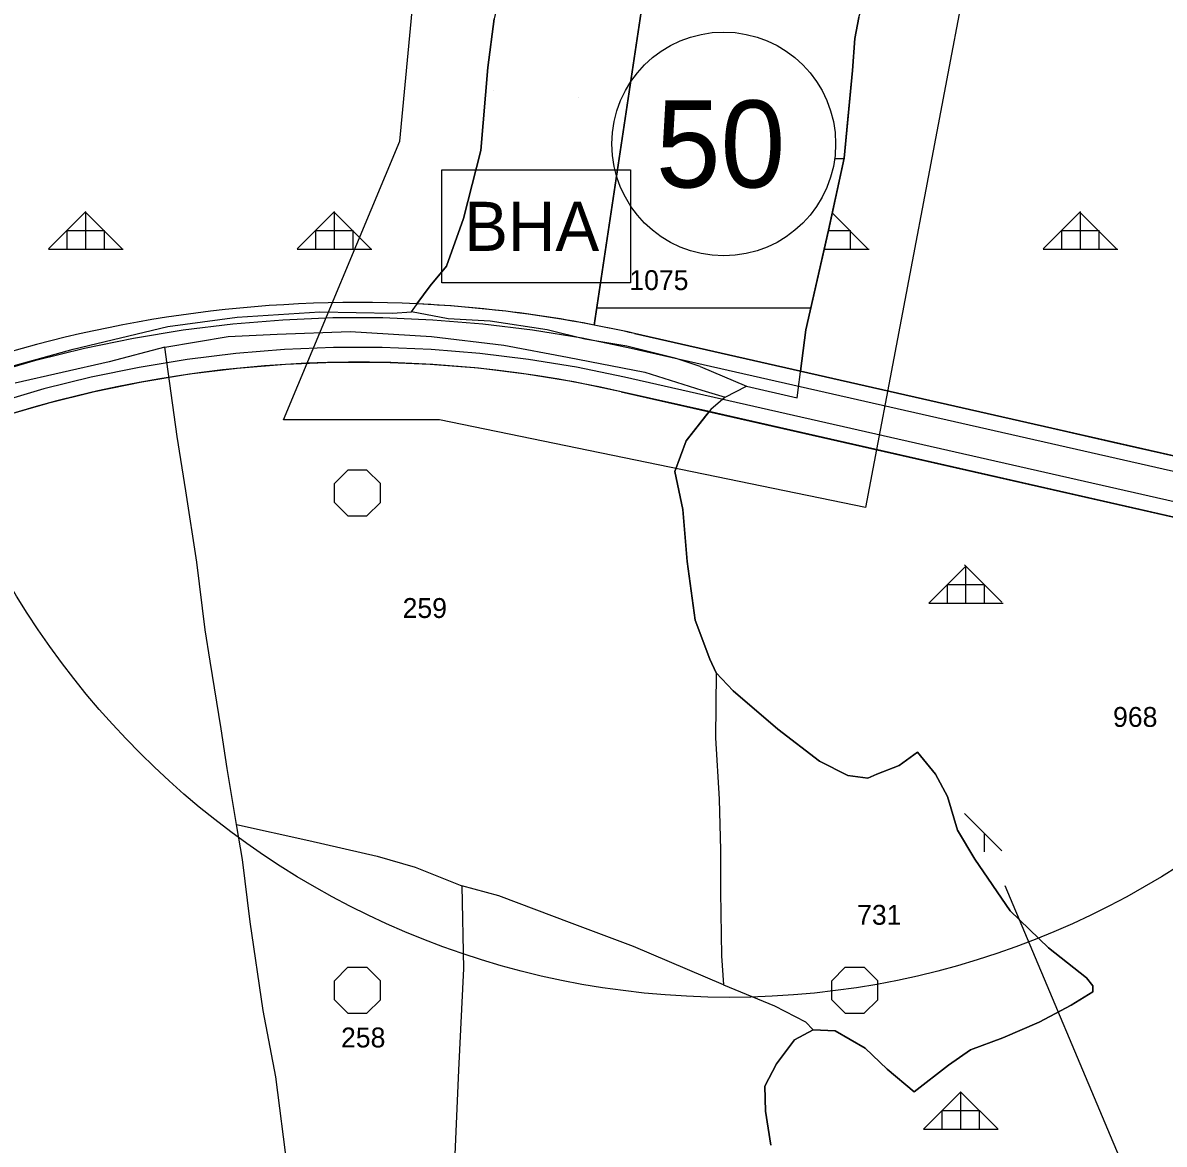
# Model space of a CAD drawing. Extents: x 410727 to 412947, y 4463506 to 4466382.
# Drawn here: x 411331.1 to 411560.6, y 4465556.3 to 4465781.8 of the extents above; entities that cross this region are included whole.
import ezdxf

# ---------------------------------------------------------------- set-up
doc = ezdxf.new("R2010")
doc.units = 0
for name, color, linetype in [('ADAKENARI', 7, 'Continuous'), ('KALDIRIM', 7, 'Continuous'), ('KDS_PARSEL_NO', 7, 'Continuous'), ('KDS_PL', 7, 'Continuous'), ('LJ_ÇERÇEVE', 7, 'Continuous'), ('PL_AYA_ORMAN', 7, 'Continuous'), ('PL_GELİŞME_KONUT', 7, 'Continuous'), ('PL_K_BHA', 7, 'Continuous'), ('PL_KA_TARIM_DIGER', 7, 'Continuous'), ('sembol', 7, 'Continuous'), ('SN_ONAMA', 7, 'Continuous'), ('TR_GELİŞME_KONUT_ÇOKAZ', 7, 'Continuous'), ('TR_ORMAN', 7, 'Continuous'), ('TR_SU_DEPOSU', 7, 'Continuous'), ('TR_TARIMALANI', 7, 'Continuous')]:
    doc.layers.add(name, color=color, linetype=linetype)

msp = doc.modelspace()

# ---------------------------------------------------------------- linework, layer by layer
at = {"layer": 'ADAKENARI'}
for p, q in [((411456.62, 4465792.14), (411445.98, 4465721.04)), ((411487.47, 4465711.77), (411454.07, 4465719.35)), ((411487.47, 4465711.77), (411454.07, 4465719.35)), ((411537.97, 4465700.31), (411487.47, 4465711.77)), ((411584.92, 4465689.65), (411487.47, 4465711.77)), ((411451.42, 4465707.64), (411569.91, 4465680.75)), ((411464.49, 4465697.73), (411469.07, 4465703.64)), ((411581.57, 4465678.11), (411469.07, 4465703.64)), ((411581.57, 4465678.11), (411469.07, 4465703.64)), ((411572.56, 4465692.45), (411537.97, 4465700.31)), ((411462.18, 4465691.6), (411464.49, 4465697.73)), ((411463.78, 4465683.97), (411462.18, 4465691.6)), ((411464.69, 4465673.53), (411463.78, 4465683.97)), ((411466.29, 4465661.68), (411464.69, 4465673.53)), ((411469.2, 4465653.84), (411466.29, 4465661.68)), ((411470.5, 4465651.13), (411469.2, 4465653.84)), ((411473.91, 4465647.51), (411470.5, 4465651.13)), ((411482.93, 4465639.78), (411473.91, 4465647.51)), ((411491.25, 4465633.35), (411482.93, 4465639.78)), ((411510.99, 4465635.16), (411507.29, 4465632.45)), ((411514.6, 4465630.74), (411510.99, 4465635.16)), ((411496.96, 4465630.44), (411491.25, 4465633.35)), ((411507.29, 4465632.45), (411502.78, 4465630.74)), ((411500.97, 4465629.94), (411496.96, 4465630.44)), ((411502.78, 4465630.74), (411500.97, 4465629.94)), ((411517.01, 4465626.22), (411514.6, 4465630.74)), ((411519.01, 4465619.5), (411517.01, 4465626.22)), ((411522.52, 4465613.67), (411519.01, 4465619.5)), ((411529.64, 4465603.23), (411522.52, 4465613.67)), ((411537.35, 4465595.79), (411529.64, 4465603.23)), ((411544.97, 4465589.77), (411537.35, 4465595.79)), ((411546.28, 4465588.16), (411544.97, 4465589.77)), ((411546.28, 4465586.96), (411546.28, 4465588.16)), ((411541.86, 4465584.25), (411546.28, 4465586.96)), ((411535.45, 4465580.83), (411541.86, 4465584.25)), ((411486.24, 4465577.32), (411490.04, 4465579.33)), ((411486.24, 4465577.32), (411490.04, 4465579.33)), ((411490.04, 4465579.33), (411494.46, 4465579.12)), ((411490.04, 4465579.33), (411494.46, 4465579.12)), ((411494.46, 4465579.12), (411500.47, 4465575.61)), ((411528.13, 4465577.72), (411535.45, 4465580.83)), ((411482.63, 4465572.5), (411486.24, 4465577.32)), ((411521.62, 4465575.31), (411528.13, 4465577.72)), ((411500.47, 4465575.61), (411504.88, 4465571.39)), ((411517.21, 4465572.19), (411521.62, 4465575.31)), ((411480.32, 4465567.98), (411482.63, 4465572.5)), ((411510.29, 4465566.87), (411517.21, 4465572.19)), ((411504.88, 4465571.39), (411510.29, 4465566.87)), ((411480.42, 4465562.96), (411480.32, 4465567.98)), ((411481.53, 4465556.12), (411480.42, 4465562.96))]:
    msp.add_line(p, q, dxfattribs=at)
for points in [[(411410.34, 4465725.3), (411412.98, 4465728.93), (411416.28, 4465732.86), (411419.73, 4465742.46), (411423.19, 4465756.15), (411424.6, 4465772.83), (411425.86, 4465782.59)], [(411499.2, 4465782.9), (411498.42, 4465778.65), (411497.95, 4465772.2), (411496.85, 4465761.03), (411496.22, 4465754.58), (411493.07, 4465740.04), (411488.52, 4465720.11), (411487.47, 4465711.77)]]:
    msp.add_lwpolyline(points, dxfattribs=at)
for radius, start, end in [(251.25, 87.2905, 108.9831), (251.25, 77.2133, 87.2905), (251.25, 77.2133, 87.2905), (239.25, 77.2133, 109.7719)]:
    msp.add_arc((411398.47, 4465474.33), radius, start, end, dxfattribs=at)
at = {"layer": 'KALDIRIM'}
for points in [[(411324.04, 4465711.16), (411333.71, 4465713.98), (411343.49, 4465716.41), (411353.36, 4465718.44), (411363.3, 4465720.07), (411373.3, 4465721.3), (411383.34, 4465722.12), (411393.41, 4465722.53), (411403.49, 4465722.53), (411413.55, 4465722.12), (411423.6, 4465721.3), (411433.6, 4465720.08), (411443.54, 4465718.45), (411453.41, 4465716.42), (411571.9, 4465689.53)], [(411570.57, 4465683.68), (411452.08, 4465710.57), (411442.45, 4465712.55), (411432.75, 4465714.14), (411422.99, 4465715.33), (411413.19, 4465716.13), (411403.37, 4465716.53), (411393.53, 4465716.53), (411383.71, 4465716.13), (411373.91, 4465715.33), (411364.15, 4465714.13), (411354.45, 4465712.54), (411344.82, 4465710.56), (411335.28, 4465708.19), (411325.84, 4465705.43)]]:
    msp.add_lwpolyline(points, dxfattribs=at)
at = {"layer": 'KDS_PL'}
for p, q in [((411424.6, 4465772.83), (411425.86, 4465782.59)), ((411498.42, 4465778.65), (411499.2, 4465782.9)), ((411497.95, 4465772.2), (411498.42, 4465778.65)), ((411423.19, 4465756.15), (411424.6, 4465772.83)), ((411496.85, 4465761.03), (411497.95, 4465772.2)), ((411496.22, 4465754.58), (411496.85, 4465761.03)), ((411419.73, 4465742.46), (411423.19, 4465756.15)), ((411493.08, 4465740.1), (411496.22, 4465754.58)), ((411416.28, 4465732.86), (411419.73, 4465742.46)), ((411488.52, 4465720.11), (411493.08, 4465740.1)), ((411412.98, 4465728.93), (411416.28, 4465732.86)), ((411409.21, 4465723.73), (411412.98, 4465728.93)), ((411374.19, 4465722.63), (411390.84, 4465723.73)), ((411390.84, 4465723.73), (411405.44, 4465723.42)), ((411405.44, 4465723.42), (411409.21, 4465723.73)), ((411416.59, 4465722.32), (411409.21, 4465723.73)), ((411360.21, 4465720.75), (411374.19, 4465722.63)), ((411425.07, 4465721.84), (411416.59, 4465722.32)), ((411436.54, 4465720.11), (411425.07, 4465721.84)), ((411341.21, 4465716.18), (411360.21, 4465720.75)), ((411372.37, 4465718.72), (411382.2, 4465719.22)), ((411382.2, 4465719.22), (411396.93, 4465719.72)), ((411396.93, 4465719.72), (411413.27, 4465718.72)), ((411444.08, 4465718.22), (411436.54, 4465720.11)), ((411486.8, 4465706.42), (411488.52, 4465720.11)), ((411359.64, 4465716.61), (411348.46, 4465713.65)), ((411359.64, 4465716.61), (411372.37, 4465718.72)), ((411360.34, 4465711.69), (411359.64, 4465716.61)), ((411413.27, 4465718.72), (411427.8, 4465717.01)), ((411427.8, 4465717.01), (411440.63, 4465714.6)), ((411452.56, 4465716.81), (411444.08, 4465718.22)), ((411462.45, 4465714.29), (411452.56, 4465716.81)), ((411317.33, 4465709.57), (411341.21, 4465716.18)), ((411440.63, 4465714.6), (411456.17, 4465711.59)), ((411467.32, 4465712.72), (411462.45, 4465714.29)), ((411348.46, 4465713.65), (411329.56, 4465709.38)), ((411467.32, 4465712.72), (411476.59, 4465708.78)), ((411362.15, 4465698.63), (411360.34, 4465711.69)), ((411456.17, 4465711.59), (411467.59, 4465707.97)), ((411467.59, 4465707.97), (411472.3, 4465706.57)), ((411472.3, 4465706.57), (411476.59, 4465708.78)), ((411476.59, 4465708.78), (411486.8, 4465706.42)), ((411472.3, 4465706.57), (411469.4, 4465704.06)), ((411469.4, 4465704.06), (411464.49, 4465697.73)), ((411363.85, 4465687.69), (411362.15, 4465698.63)), ((411464.49, 4465697.73), (411462.18, 4465691.6)), ((411462.18, 4465691.6), (411463.78, 4465683.97)), ((411366.06, 4465673.33), (411363.85, 4465687.69)), ((411463.78, 4465683.97), (411464.69, 4465673.53)), ((411367.76, 4465659.77), (411366.06, 4465673.33)), ((411464.69, 4465673.53), (411466.29, 4465661.68)), ((411466.29, 4465661.68), (411469.2, 4465653.84)), ((411368.76, 4465653.44), (411367.76, 4465659.77)), ((411370.97, 4465639.88), (411368.76, 4465653.44)), ((411469.2, 4465653.84), (411470.5, 4465651.13)), ((411470.5, 4465651.13), (411470.4, 4465638.07)), ((411473.91, 4465647.51), (411470.5, 4465651.13)), ((411482.93, 4465639.78), (411473.91, 4465647.51)), ((411372.17, 4465631.85), (411370.97, 4465639.88)), ((411491.25, 4465633.35), (411482.93, 4465639.78)), ((411470.4, 4465638.07), (411471.1, 4465625.72)), ((411510.99, 4465635.16), (411507.29, 4465632.45)), ((411514.6, 4465630.74), (411510.99, 4465635.16)), ((411374.08, 4465620.6), (411372.17, 4465631.85)), ((411496.96, 4465630.44), (411491.25, 4465633.35)), ((411507.29, 4465632.45), (411502.78, 4465630.74)), ((411500.97, 4465629.94), (411496.96, 4465630.44)), ((411502.78, 4465630.74), (411500.97, 4465629.94)), ((411517.01, 4465626.22), (411514.6, 4465630.74)), ((411471.1, 4465625.72), (411471.4, 4465615.48)), ((411519.01, 4465619.5), (411517.01, 4465626.22)), ((411375.28, 4465613.57), (411374.08, 4465620.6)), ((411374.08, 4465620.6), (411388.61, 4465617.39)), ((411522.52, 4465613.67), (411519.01, 4465619.5)), ((411388.61, 4465617.39), (411402.34, 4465614.27)), ((411376.78, 4465601.02), (411375.28, 4465613.57)), ((411402.34, 4465614.27), (411409.96, 4465612.06)), ((411471.4, 4465615.48), (411471.4, 4465607.04)), ((411529.64, 4465603.23), (411522.52, 4465613.67)), ((411409.96, 4465612.06), (411419.38, 4465608.25)), ((411426.8, 4465606.24), (411419.38, 4465608.25)), ((411419.38, 4465608.25), (411419.68, 4465591.68)), ((411471.4, 4465607.04), (411471.6, 4465594.19)), ((411441.53, 4465600.72), (411426.8, 4465606.24)), ((411537.35, 4465595.79), (411529.64, 4465603.23)), ((411379.39, 4465583.24), (411376.78, 4465601.02)), ((411453.86, 4465596.1), (411441.53, 4465600.72)), ((411472, 4465588.36), (411453.86, 4465596.1)), ((411544.97, 4465589.77), (411537.35, 4465595.79)), ((411471.6, 4465594.19), (411472, 4465588.36)), ((411419.68, 4465591.68), (411418.68, 4465571.19)), ((411472, 4465588.36), (411482.23, 4465584.14)), ((411546.28, 4465588.16), (411544.97, 4465589.77)), ((411546.28, 4465586.96), (411546.28, 4465588.16)), ((411541.86, 4465584.25), (411546.28, 4465586.96)), ((411482.23, 4465584.14), (411488.44, 4465580.93)), ((411535.45, 4465580.83), (411541.86, 4465584.25)), ((411381.99, 4465569.88), (411379.39, 4465583.24)), ((411486.24, 4465577.32), (411490.04, 4465579.33)), ((411488.44, 4465580.93), (411490.04, 4465579.33)), ((411490.04, 4465579.33), (411494.46, 4465579.12)), ((411494.46, 4465579.12), (411500.47, 4465575.61)), ((411528.13, 4465577.72), (411535.45, 4465580.83)), ((411482.63, 4465572.5), (411486.24, 4465577.32)), ((411521.62, 4465575.31), (411528.13, 4465577.72)), ((411500.47, 4465575.61), (411504.88, 4465571.39)), ((411517.21, 4465572.19), (411521.62, 4465575.31)), ((411480.32, 4465567.98), (411482.63, 4465572.5)), ((411510.29, 4465566.87), (411517.21, 4465572.19)), ((411384.3, 4465551.5), (411381.99, 4465569.88)), ((411418.68, 4465571.19), (411417.78, 4465550.1)), ((411504.88, 4465571.39), (411510.29, 4465566.87)), ((411480.42, 4465562.96), (411480.32, 4465567.98)), ((411481.53, 4465556.12), (411480.42, 4465562.96))]:
    msp.add_line(p, q, dxfattribs=at)
at = {"layer": 'LJ_ÇERÇEVE'}
msp.add_line((412177.76, 4464068.35), (411528.62, 4465608.26), dxfattribs=at)
msp.add_circle((411473.17, 4465753.45), 167.6, dxfattribs=at)
at = {"layer": 'PL_AYA_ORMAN'}
for points in [[(411410.34, 4465725.3), (411410.34, 4465725.3), (411410.34, 4465725.3), (411412.98, 4465728.93), (411416.28, 4465732.86), (411419.73, 4465742.46), (411423.19, 4465756.15), (411424.6, 4465772.83), (411425.86, 4465782.59)], [(411499.2, 4465782.9), (411498.42, 4465778.65), (411497.95, 4465772.2), (411496.22, 4465754.58), (411493.08, 4465740.1), (411488.52, 4465720.11), (411487.47, 4465711.77), (411537.97, 4465700.31), (411550.26, 4465697.52), (411572.56, 4465692.45), (411584.92, 4465689.65), (411603.17, 4465683.15), (411648.41, 4465667.03), (411663.23, 4465672.82), (411665.57, 4465677.27)], [(411569.91, 4465680.75), (411469.07, 4465703.64), (411464.49, 4465697.73), (411462.18, 4465691.6), (411463.78, 4465683.97), (411464.69, 4465673.53), (411466.29, 4465661.68), (411469.2, 4465653.84), (411470.5, 4465651.13), (411473.91, 4465647.51), (411482.93, 4465639.78), (411491.25, 4465633.35), (411496.96, 4465630.44), (411500.97, 4465629.94), (411502.78, 4465630.74), (411507.29, 4465632.45), (411510.99, 4465635.16), (411514.6, 4465630.74), (411517.01, 4465626.22), (411519.01, 4465619.5), (411522.52, 4465613.67), (411529.64, 4465603.23), (411537.35, 4465595.79), (411544.97, 4465589.77), (411546.28, 4465588.16), (411546.28, 4465586.96), (411541.86, 4465584.25), (411535.45, 4465580.83), (411528.13, 4465577.72), (411521.62, 4465575.31), (411517.21, 4465572.19), (411510.29, 4465566.87), (411504.88, 4465571.39), (411500.47, 4465575.61), (411494.46, 4465579.12), (411490.04, 4465579.33), (411486.24, 4465577.32), (411482.63, 4465572.5), (411480.32, 4465567.98), (411480.42, 4465562.96), (411481.53, 4465556.12)]]:
    msp.add_lwpolyline(points, dxfattribs=at)
msp.add_arc((411398.47, 4465474.33), 251.25, 87.2906, 108.9831, dxfattribs=at)
at = {"layer": 'PL_GELİŞME_KONUT'}
msp.add_lwpolyline([(411454.07, 4465719.35), (411454.07, 4465719.35), (411487.47, 4465711.77), (411488.52, 4465720.11), (411493.07, 4465740.04), (411493.07, 4465740.06), (411493.08, 4465740.1), (411496.22, 4465754.58), (411496.85, 4465761.03), (411497.95, 4465772.2), (411498.42, 4465778.65), (411499.2, 4465782.9), (411500.15, 4465786.21), (411497.5, 4465787.74), (411496.06, 4465788.57), (411494.49, 4465789.35), (411483.97, 4465792.19), (411478.16, 4465792.03), (411465.59, 4465792.34), (411456.62, 4465792.12), (411445.98, 4465721.04), (411445.98, 4465721.04)], dxfattribs=at)
msp.add_arc((411398.47, 4465474.33), 251.25, 77.2133, 79.099, dxfattribs=at)
at = {"layer": 'PL_K_BHA'}
msp.add_lwpolyline([(411445.98, 4465721.04), (411456.62, 4465792.12), (411452.87, 4465792.03), (411440.46, 4465789.51), (411433.96, 4465787.81), (411426.64, 4465785.89), (411425.86, 4465782.59), (411424.6, 4465772.83), (411423.19, 4465756.15), (411419.73, 4465742.46), (411416.28, 4465732.86), (411412.98, 4465728.93), (411410.34, 4465725.3), (411410.34, 4465725.3)], dxfattribs=at)
msp.add_arc((411398.47, 4465474.33), 251.25, 79.099, 87.2905, dxfattribs=at)
at = {"layer": 'PL_KA_TARIM_DIGER'}
for points in [[(411469.07, 4465703.64), (411451.42, 4465707.64), (411441.91, 4465709.6), (411432.32, 4465711.17), (411422.69, 4465712.35), (411413.01, 4465713.13), (411403.31, 4465713.53), (411393.59, 4465713.53), (411383.89, 4465713.13), (411374.21, 4465712.34), (411364.58, 4465711.16), (411354.99, 4465709.59), (411345.48, 4465707.64), (411336.06, 4465705.29), (411326.74, 4465702.57)], [(411481.53, 4465556.12), (411480.42, 4465562.96), (411480.32, 4465567.98), (411482.63, 4465572.5), (411486.24, 4465577.32), (411490.04, 4465579.33), (411494.46, 4465579.12), (411500.47, 4465575.61), (411504.88, 4465571.39), (411510.29, 4465566.87), (411517.21, 4465572.19), (411521.62, 4465575.31), (411528.13, 4465577.72), (411535.45, 4465580.83), (411541.86, 4465584.25), (411546.28, 4465586.96), (411546.28, 4465588.16), (411544.97, 4465589.77), (411537.35, 4465595.79), (411529.64, 4465603.23), (411522.52, 4465613.67), (411519.01, 4465619.5), (411517.01, 4465626.22), (411514.6, 4465630.74), (411510.99, 4465635.16), (411507.29, 4465632.45), (411502.78, 4465630.74), (411500.97, 4465629.94), (411496.96, 4465630.44), (411491.25, 4465633.35), (411482.93, 4465639.78), (411473.91, 4465647.51), (411470.5, 4465651.13), (411469.2, 4465653.84), (411466.29, 4465661.68), (411464.69, 4465673.53), (411463.78, 4465683.97), (411462.18, 4465691.6), (411464.49, 4465697.73), (411469.07, 4465703.64)]]:
    msp.add_lwpolyline(points, dxfattribs=at)
at = {"layer": 'sembol'}
for p, q in [((411415.33, 4465752.29), (411453.29, 4465752.29)), ((411415.33, 4465729.51), (411415.33, 4465752.29)), ((411453.29, 4465752.29), (411453.29, 4465729.51)), ((411453.29, 4465729.51), (411415.33, 4465729.51))]:
    msp.add_line(p, q, dxfattribs=at)
msp.add_circle((411472.03, 4465757.46), 22.5, dxfattribs=at)
at = {"layer": 'SN_ONAMA'}
msp.add_lwpolyline([(411383.47, 4465701.98), (411406.89, 4465758.05), (411410.6, 4465797.01), (411446.38, 4465807.63), (411485.88, 4465807.28), (411522.02, 4465797.82), (411500.54, 4465684.33), (411414.88, 4465701.98)], close=True, dxfattribs=at)
at = {"layer": 'TR_GELİŞME_KONUT_ÇOKAZ'}
for p, q in [((411494.34, 4465754.54), (411496.22, 4465754.54)), ((411446.5, 4465724.54), (411489.53, 4465724.54))]:
    msp.add_line(p, q, dxfattribs=at)
at = {"layer": 'TR_ORMAN'}
for p, q in [((411336.24, 4465736.37), (411343.74, 4465743.87)), ((411351.12, 4465736.31), (411343.62, 4465743.81)), ((411343.75, 4465736.29), (411343.75, 4465743.79)), ((411386.24, 4465736.38), (411393.74, 4465743.88)), ((411401.11, 4465736.31), (411393.61, 4465743.81)), ((411393.75, 4465736.29), (411393.75, 4465743.79)), ((411501.1, 4465736.31), (411493.83, 4465743.58)), ((411536.24, 4465736.4), (411543.74, 4465743.9)), ((411551.09, 4465736.31), (411543.59, 4465743.81)), ((411543.75, 4465736.29), (411543.75, 4465743.79)), ((411340, 4465736.29), (411340, 4465740.04)), ((411340, 4465740.04), (411347.5, 4465740.04)), ((411347.5, 4465736.29), (411347.5, 4465740.04)), ((411390, 4465736.29), (411390, 4465740.04)), ((411390, 4465740.04), (411397.5, 4465740.04)), ((411397.5, 4465736.29), (411397.5, 4465740.04)), ((411493.07, 4465740.04), (411497.5, 4465740.04)), ((411497.5, 4465736.29), (411497.5, 4465740.04)), ((411540, 4465736.29), (411540, 4465740.04)), ((411540, 4465740.04), (411547.5, 4465740.04)), ((411547.5, 4465736.29), (411547.5, 4465740.04)), ((411336.25, 4465736.29), (411351.25, 4465736.29)), ((411386.25, 4465736.29), (411401.25, 4465736.29)), ((411492.21, 4465736.29), (411501.25, 4465736.29)), ((411536.25, 4465736.29), (411551.25, 4465736.29)), ((411513.24, 4465665.09), (411520.74, 4465672.59)), ((411527.93, 4465665.35), (411520.44, 4465672.85)), ((411520.74, 4465665.13), (411520.74, 4465672.63)), ((411516.99, 4465665.13), (411516.99, 4465668.88)), ((411516.99, 4465668.88), (411524.49, 4465668.88)), ((411524.49, 4465665.13), (411524.49, 4465668.88)), ((411513.24, 4465665.13), (411528.24, 4465665.13)), ((411527.97, 4465615.33), (411520.47, 4465622.83)), ((411524.49, 4465615.13), (411524.49, 4465618.88)), ((411512.18, 4465559.36), (411519.68, 4465566.86)), ((411527.14, 4465559.38), (411519.64, 4465566.88)), ((411519.68, 4465559.36), (411519.68, 4465566.86)), ((411515.93, 4465563.11), (411523.43, 4465563.11)), ((411515.93, 4465559.36), (411515.93, 4465563.11)), ((411523.43, 4465559.36), (411523.43, 4465563.11)), ((411512.18, 4465559.36), (411527.18, 4465559.36))]:
    msp.add_line(p, q, dxfattribs=at)
at = {"layer": 'TR_SU_DEPOSU'}
for p, q in [((411425.65, 4465768.19), (411425.65, 4465768.19)), ((411442.85, 4465766.87), (411442.85, 4465766.87)), ((411425.65, 4465743.19), (411425.65, 4465743.19)), ((411442.85, 4465741.87), (411442.85, 4465741.87))]:
    msp.add_line(p, q, dxfattribs=at)
at = {"layer": 'TR_TARIMALANI'}
for p, q in [((411393.75, 4465689.19), (411396.45, 4465691.89)), ((411393.75, 4465689.19), (411396.45, 4465691.89)), ((411396.46, 4465691.9), (411400.29, 4465691.9)), ((411396.46, 4465691.9), (411400.29, 4465691.9)), ((411403, 4465689.19), (411400.29, 4465691.89)), ((411403, 4465689.19), (411400.29, 4465691.89)), ((411403, 4465689.19), (411400.29, 4465691.89)), ((411403, 4465689.19), (411400.29, 4465691.89)), ((411393.75, 4465685.36), (411393.75, 4465689.19)), ((411393.75, 4465685.36), (411393.75, 4465689.19)), ((411403, 4465685.36), (411403, 4465689.19)), ((411403, 4465685.36), (411403, 4465689.19)), ((411396.46, 4465682.65), (411393.75, 4465685.35)), ((411396.46, 4465682.65), (411393.75, 4465685.35)), ((411400.29, 4465682.65), (411402.99, 4465685.35)), ((411400.29, 4465682.65), (411402.99, 4465685.35)), ((411396.46, 4465682.65), (411400.29, 4465682.65)), ((411396.46, 4465682.65), (411400.29, 4465682.65)), ((411393.75, 4465589.19), (411396.45, 4465591.9)), ((411393.75, 4465589.19), (411396.45, 4465591.9)), ((411396.46, 4465591.9), (411400.29, 4465591.9)), ((411396.46, 4465591.9), (411400.29, 4465591.9)), ((411403, 4465589.19), (411400.29, 4465591.9)), ((411403, 4465589.19), (411400.29, 4465591.9)), ((411493.74, 4465589.19), (411496.45, 4465591.9)), ((411493.74, 4465589.19), (411496.45, 4465591.9)), ((411496.46, 4465591.9), (411500.29, 4465591.9)), ((411496.46, 4465591.9), (411500.29, 4465591.9)), ((411502.99, 4465589.19), (411500.29, 4465591.9)), ((411502.99, 4465589.19), (411500.29, 4465591.9)), ((411502.99, 4465589.19), (411500.29, 4465591.9)), ((411502.99, 4465589.19), (411500.29, 4465591.9)), ((411393.75, 4465585.36), (411393.75, 4465589.19)), ((411393.75, 4465585.36), (411393.75, 4465589.19)), ((411403, 4465585.36), (411403, 4465589.19)), ((411403, 4465585.36), (411403, 4465589.19)), ((411493.75, 4465585.36), (411493.75, 4465589.19)), ((411493.75, 4465585.36), (411493.75, 4465589.19)), ((411493.75, 4465585.36), (411493.75, 4465589.19)), ((411493.75, 4465585.36), (411493.75, 4465589.19)), ((411503, 4465585.36), (411503, 4465589.19)), ((411503, 4465585.36), (411503, 4465589.19)), ((411396.46, 4465582.65), (411393.75, 4465585.36)), ((411396.46, 4465582.65), (411393.75, 4465585.36)), ((411400.29, 4465582.65), (411402.99, 4465585.36)), ((411400.29, 4465582.65), (411402.99, 4465585.36)), ((411496.45, 4465582.65), (411493.75, 4465585.36)), ((411496.45, 4465582.65), (411493.75, 4465585.36)), ((411500.28, 4465582.65), (411502.99, 4465585.36)), ((411500.28, 4465582.65), (411502.99, 4465585.36)), ((411396.46, 4465582.65), (411400.29, 4465582.65)), ((411396.46, 4465582.65), (411400.29, 4465582.65)), ((411496.46, 4465582.65), (411500.29, 4465582.65)), ((411496.46, 4465582.65), (411500.29, 4465582.65))]:
    msp.add_line(p, q, dxfattribs=at)

# ---------------------------------------------------------------- texts
at = {"layer": 'KDS_PARSEL_NO'}
for s, p in [('1075', (411453.04, 4465728.08)), ('259', (411407.45, 4465662.14)), ('968', (411550.31, 4465640.24)), ('731', (411498.84, 4465600.45)), ('258', (411395.07, 4465575.78))]:
    msp.add_text(s, height=4, dxfattribs=at).set_placement(p)
at = {"layer": 'sembol'}
for s, height, p in [('50', 17.5, (411458.37, 4465748.71)), ('BHA', 9.869, (411419.84, 4465735.96))]:
    msp.add_text(s, height=height, dxfattribs=at).set_placement(p)

doc.saveas('drawing.dxf')
